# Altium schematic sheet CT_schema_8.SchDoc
size 287 x 160 mm
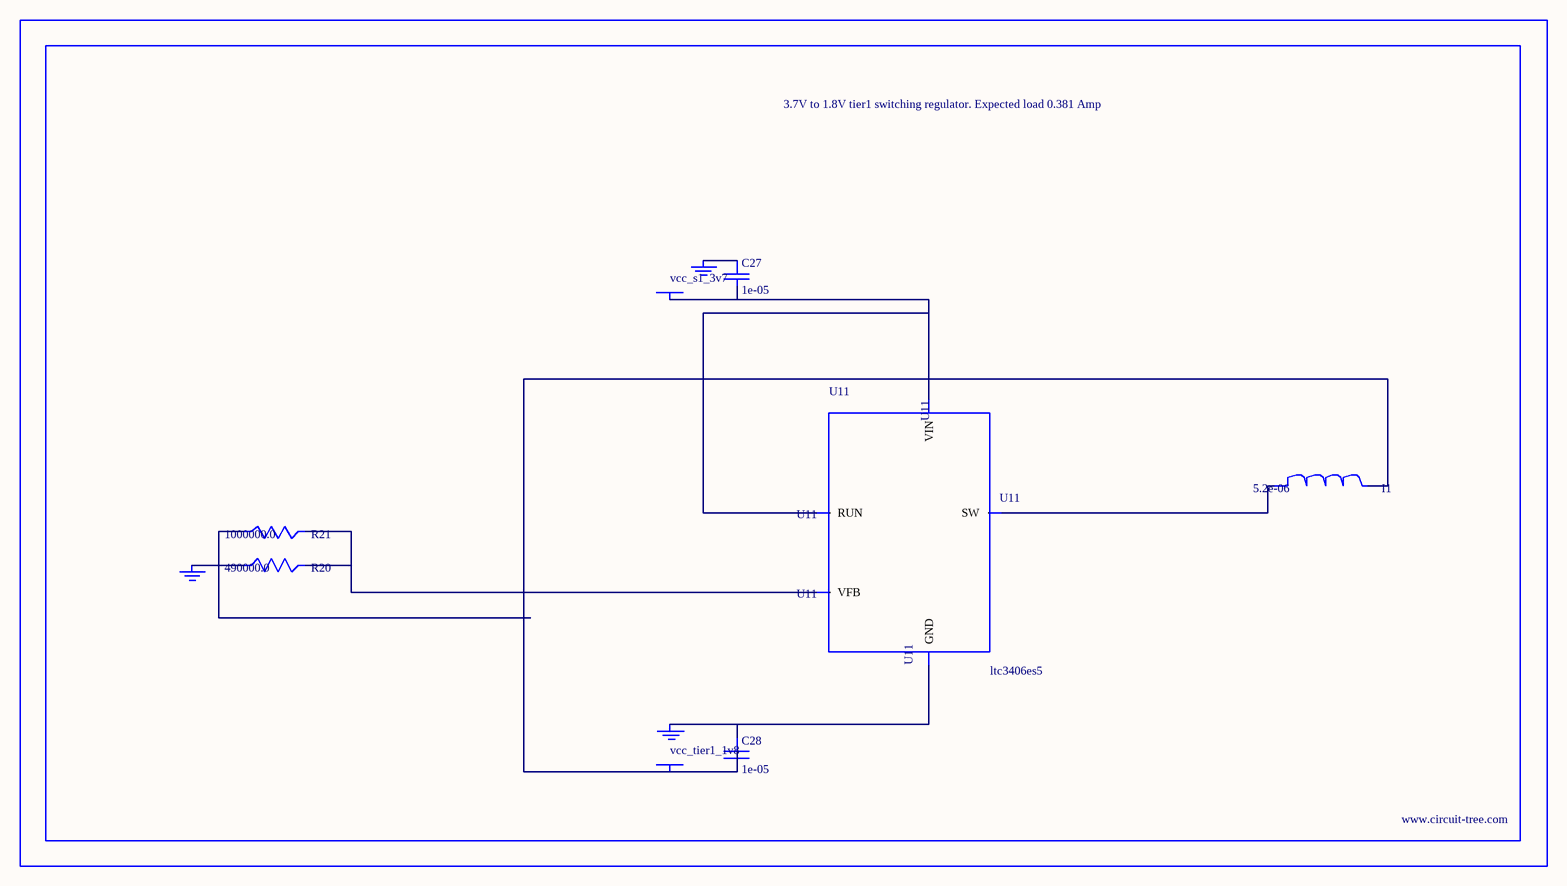
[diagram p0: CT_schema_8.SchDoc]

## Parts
BORDER7  (no value)
C27  1e-05  [C0805]
C28  1e-05  [C0805]
GND_INSTANCE_7_0  (no value)
GND_INSTANCE_7_1  (no value)
GND_INSTANCE_7_2  (no value)
I1  5.2e-06  [DR1040]
POWER_INSTANCE_7_0  vcc_tier1_1v8
POWER_INSTANCE_7_1  vcc_s1_3v7
R20  490000.0  [R0603]
R21  1000000.0  [R0603]
U11  ltc3406es5  [TSOT-23-5]

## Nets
NetC27_1: C27.1 GND_INSTANCE_7_1.0(GND)
NetC27_2: C27.2 POWER_INSTANCE_7_1.0(PWR) U11.1(RUN) U11.4(VIN)
NetC28_1: C28.1 GND_INSTANCE_7_0.0(GND) U11.2(GND)
NetC28_2: C28.2 I1.2 POWER_INSTANCE_7_0.0(PWR) R21.1
NetGND_INSTANCE_7_2_0: GND_INSTANCE_7_2.0(GND) R20.1
NetI1_1: I1.1 U11.3(SW)
NetR20_2: R20.2 R21.2 U11.5(VFB)

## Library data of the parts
BORDER7 = BORDER_PAGE7
C27 C28 = C0805C106K8RACTU
GND_INSTANCE_7_0-GND_INSTANCE_7_2 = GND
I1 = DR1040-5R2-R
POWER_INSTANCE_7_0 POWER_INSTANCE_7_1 = PWR
R20 = R20
R21 = RC0603JR-071ML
